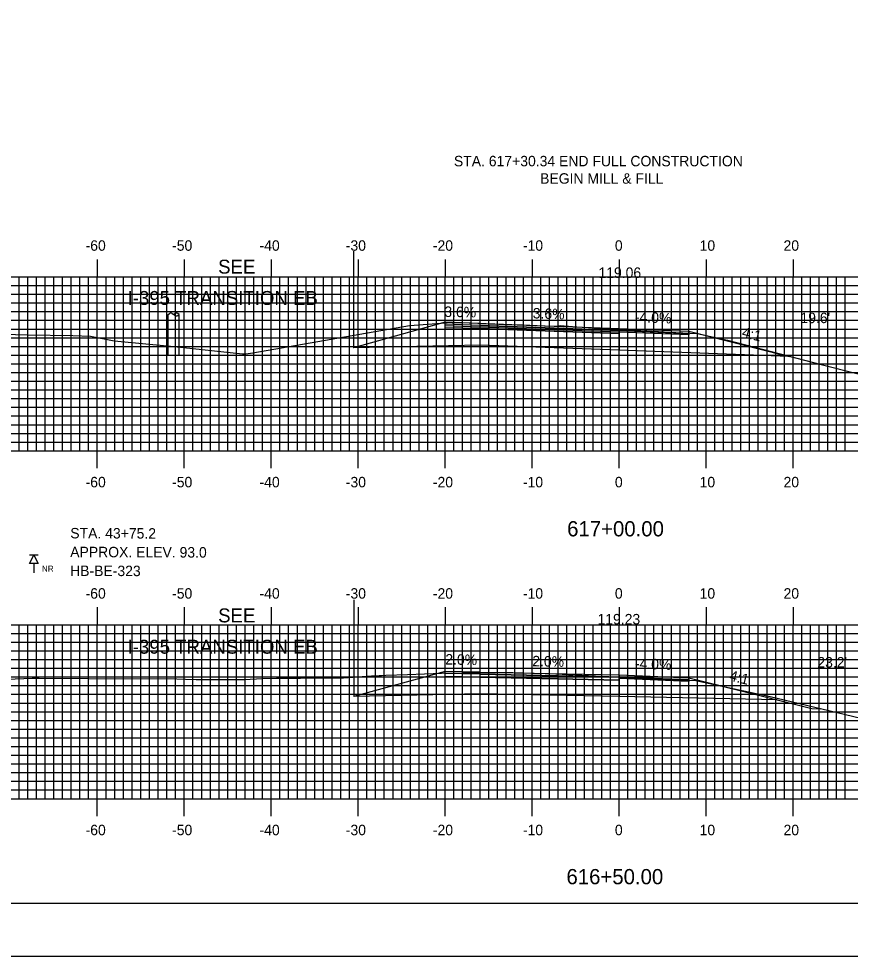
# Model space of a CAD drawing. Extents: x 844930 to 845273, y 363538 to 363758.
# Drawn here: x 845026.4 to 845122, y 363537.6 to 363645.4 of the extents above; entities that cross this region are included whole.
import ezdxf

# ---------------------------------------------------------------- set-up
doc = ezdxf.new("R2010")
doc.units = 0
for name, color, linetype in [('ANNOTATION', 7, 'Continuous'), ('BORDER', 7, 'Continuous'), ('BORING - NO REFUSAL', 7, 'Continuous'), ('D_Drainage_Text', 7, 'Continuous'), ('D_Roadway_Centerline_Text', 7, 'Continuous'), ('D_Roadway_Edge_Shoulder', 7, 'Continuous'), ('D_Roadway_Edge_TW', 7, 'Continuous'), ('D_Roadway_FinishedGrade', 7, 'Continuous'), ('D_Roadway_Pavement', 7, 'Continuous'), ('D_Roadway_SlopeLines', 7, 'Continuous'), ('D_Roadway_SubGrade', 7, 'Continuous'), ('D_Text_Standard', 7, 'Continuous'), ('H_V ANNOTATION', 7, 'Continuous'), ('M_Roadway_Centerline', 7, 'Continuous'), ('MAJOR', 7, 'Continuous'), ('MINOR', 7, 'Continuous'), ('PLOT BOUNDARY', 7, 'Continuous'), ('S_Roadway_Centerline', 7, 'Continuous'), ('S_Utilities_Pole_StreetLight', 7, 'Continuous')]:
    doc.layers.add(name, color=color, linetype=linetype)

msp = doc.modelspace()

# ---------------------------------------------------------------- linework, layer by layer
at = {"layer": 'BORDER'}
msp.add_lwpolyline([(844945.88, 363543.72), (845265.88, 363543.72), (845265.88, 363753.72), (844945.88, 363753.72)], close=True, dxfattribs=at)
at = {"layer": 'BORING - NO REFUSAL'}
for p, q in [((845028.66, 363583.72), (845027.7, 363583.72)), ((845028.18, 363582.76), (845028.18, 363581.7))]:
    msp.add_line(p, q, dxfattribs=at)
msp.add_lwpolyline([(845028.18, 363583.72), (845028.66, 363582.76), (845027.7, 363582.76)], close=True, dxfattribs=at)
at = {"layer": 'D_Roadway_Edge_Shoulder'}
for points in [[(845095.48, 363609.79), (845103.48, 363609.47), (845103.48, 363609.22), (845095.48, 363609.54)], [(845095.48, 363569.95), (845103.48, 363569.63), (845103.48, 363569.38), (845095.48, 363569.7)]]:
    msp.add_lwpolyline(points, close=True, dxfattribs=at)
at = {"layer": 'D_Roadway_Edge_TW'}
for points in [[(845079.48, 363610.36), (845095.48, 363609.79), (845095.48, 363609.54), (845079.48, 363610.11)], [(845079.48, 363570.27), (845095.48, 363569.95), (845095.48, 363569.7), (845079.48, 363570.02)]]:
    msp.add_lwpolyline(points, close=True, dxfattribs=at)
at = {"layer": 'D_Roadway_FinishedGrade'}
for p, q in [((845079.48, 363610.11), (845075.48, 363610.26)), ((845095.48, 363609.37), (845079.48, 363609.95)), ((845079.48, 363607.86), (845064.95, 363607.57)), ((845079.48, 363570.27), (845075.48, 363570.35)), ((845079.48, 363570.02), (845075.48, 363570.1)), ((845079.48, 363567.77), (845064.96, 363567.48))]:
    msp.add_line(p, q, dxfattribs=at)
for points in [[(845079.48, 363610.36), (845075.48, 363610.51), (845064.95, 363607.57)], [(845079.48, 363609.95), (845079.48, 363609.95), (845075.48, 363610.09), (845075.48, 363610.51)], [(845079.48, 363609.78), (845075.48, 363609.86), (845075.48, 363610.09)], [(845079.48, 363569.68), (845075.48, 363569.76), (845075.48, 363570.35), (845064.96, 363567.48)], [(845113.65, 363567.08), (845117.65, 363566.08), (845118.68, 363566.06)]]:
    msp.add_lwpolyline(points, dxfattribs=at)
at = {"layer": 'D_Roadway_Pavement'}
for points in [[(845079.48, 363610.11), (845095.48, 363609.54), (845095.48, 363609.2), (845079.48, 363609.78)], [(845095.48, 363609.54), (845103.48, 363609.22), (845103.48, 363609.05), (845095.48, 363609.37)], [(845079.48, 363570.02), (845095.48, 363569.7), (845095.48, 363569.36), (845079.48, 363569.68)], [(845095.48, 363569.7), (845103.48, 363569.38), (845103.48, 363569.21), (845095.48, 363569.53)]]:
    msp.add_lwpolyline(points, close=True, dxfattribs=at)
for points in [[(845095.48, 363609.54), (845095.48, 363609.2)], [(845095.48, 363609.54), (845095.48, 363609.2)], [(845095.48, 363569.7), (845095.48, 363569.36)], [(845095.48, 363569.7), (845095.48, 363569.36)]]:
    msp.add_lwpolyline(points, dxfattribs=at)
at = {"layer": 'D_Roadway_SlopeLines'}
for points in [[(845103.48, 363609.47), (845104.98, 363609.09)], [(845103.48, 363569.63), (845107.57, 363568.6)]]:
    msp.add_lwpolyline(points, dxfattribs=at)
at = {"layer": 'D_Roadway_SubGrade'}
for p, q in [((845064.95, 363618.67), (845064.95, 363607.57)), ((845064.96, 363578.57), (845064.96, 363567.48))]:
    msp.add_line(p, q, dxfattribs=at)
for points in [[(845079.48, 363609.78), (845095.48, 363609.2), (845095.48, 363607.29), (845079.48, 363607.86)], [(845095.48, 363609.2), (845095.48, 363609.54), (845103.48, 363609.22), (845103.48, 363609.47), (845115.03, 363606.58), (845095.48, 363607.29)], [(845079.48, 363569.68), (845095.48, 363569.36), (845095.48, 363567.45), (845079.48, 363567.77)], [(845095.48, 363569.36), (845095.48, 363569.7), (845103.48, 363569.38), (845103.48, 363569.63), (845113.65, 363567.08), (845095.48, 363567.45)]]:
    msp.add_lwpolyline(points, close=True, dxfattribs=at)
at = {"layer": 'MAJOR'}
for p, q in [((845035.48, 363617.73), (845035.48, 363615.72)), ((845045.48, 363617.73), (845045.48, 363615.72)), ((845055.48, 363617.73), (845055.48, 363615.72)), ((845065.48, 363617.73), (845065.48, 363615.72)), ((845075.48, 363617.73), (845075.48, 363615.72)), ((845085.48, 363617.73), (845085.48, 363615.72)), ((845095.48, 363617.73), (845095.48, 363615.72)), ((845105.48, 363617.73), (845105.48, 363615.72)), ((845115.48, 363617.73), (845115.48, 363615.72)), ((844955.48, 363615.72), (845235.48, 363615.72)), ((844955.48, 363615.72), (845235.48, 363615.72)), ((845035.48, 363595.72), (845035.48, 363615.72)), ((845045.48, 363595.72), (845045.48, 363615.72)), ((845055.48, 363595.72), (845055.48, 363615.72)), ((845065.48, 363595.72), (845065.48, 363615.72)), ((845075.48, 363595.72), (845075.48, 363615.72)), ((845085.48, 363595.72), (845085.48, 363615.72)), ((845095.48, 363595.72), (845095.48, 363615.72)), ((845105.48, 363595.72), (845105.48, 363615.72)), ((845115.48, 363595.72), (845115.48, 363615.72)), ((844955.48, 363610.72), (845235.48, 363610.72)), ((844955.48, 363605.72), (845235.48, 363605.72)), ((844955.48, 363600.72), (845235.48, 363600.72)), ((844955.48, 363595.72), (845235.48, 363595.72)), ((844955.48, 363595.72), (845235.48, 363595.72)), ((845035.48, 363593.72), (845035.48, 363595.72)), ((845045.48, 363593.72), (845045.48, 363595.72)), ((845055.48, 363593.72), (845055.48, 363595.72)), ((845065.48, 363593.72), (845065.48, 363595.72)), ((845075.48, 363593.72), (845075.48, 363595.72)), ((845085.48, 363593.72), (845085.48, 363595.72)), ((845095.48, 363593.72), (845095.48, 363595.72)), ((845105.48, 363593.72), (845105.48, 363595.72)), ((845115.48, 363593.72), (845115.48, 363595.72)), ((845035.48, 363577.73), (845035.48, 363575.72)), ((845045.48, 363577.73), (845045.48, 363575.72)), ((845055.48, 363577.73), (845055.48, 363575.72)), ((845065.48, 363577.73), (845065.48, 363575.72)), ((845075.48, 363577.73), (845075.48, 363575.72)), ((845085.48, 363577.73), (845085.48, 363575.72)), ((845095.48, 363577.73), (845095.48, 363575.72)), ((845105.48, 363577.73), (845105.48, 363575.72)), ((845115.48, 363577.73), (845115.48, 363575.72)), ((844955.48, 363575.72), (845235.48, 363575.72)), ((844955.48, 363575.72), (845235.48, 363575.72)), ((845035.48, 363555.72), (845035.48, 363575.72)), ((845045.48, 363555.72), (845045.48, 363575.72)), ((845055.48, 363555.72), (845055.48, 363575.72)), ((845065.48, 363555.72), (845065.48, 363575.72)), ((845075.48, 363555.72), (845075.48, 363575.72)), ((845085.48, 363555.72), (845085.48, 363575.72)), ((845095.48, 363555.72), (845095.48, 363575.72)), ((845105.48, 363555.72), (845105.48, 363575.72)), ((845115.48, 363555.72), (845115.48, 363575.72)), ((844955.48, 363570.72), (845235.48, 363570.72)), ((844955.48, 363565.72), (845235.48, 363565.72)), ((844955.48, 363560.72), (845235.48, 363560.72)), ((844955.48, 363555.72), (845235.48, 363555.72)), ((844955.48, 363555.72), (845235.48, 363555.72)), ((845035.48, 363553.72), (845035.48, 363555.72)), ((845045.48, 363553.72), (845045.48, 363555.72)), ((845055.48, 363553.72), (845055.48, 363555.72)), ((845065.48, 363553.72), (845065.48, 363555.72)), ((845075.48, 363553.72), (845075.48, 363555.72)), ((845085.48, 363553.72), (845085.48, 363555.72)), ((845095.48, 363553.72), (845095.48, 363555.72)), ((845105.48, 363553.72), (845105.48, 363555.72)), ((845115.48, 363553.72), (845115.48, 363555.72))]:
    msp.add_line(p, q, dxfattribs=at)
at = {"layer": 'MINOR'}
for p, q in [((845026.48, 363595.72), (845026.48, 363615.72)), ((845027.48, 363595.72), (845027.48, 363615.72)), ((845028.48, 363595.72), (845028.48, 363615.72)), ((845029.48, 363595.72), (845029.48, 363615.72)), ((845030.48, 363595.72), (845030.48, 363615.72)), ((845031.48, 363595.72), (845031.48, 363615.72)), ((845032.48, 363595.72), (845032.48, 363615.72)), ((845033.48, 363595.72), (845033.48, 363615.72)), ((845034.48, 363595.72), (845034.48, 363615.72)), ((845036.48, 363595.72), (845036.48, 363615.72)), ((845037.48, 363595.72), (845037.48, 363615.72)), ((845038.48, 363595.72), (845038.48, 363615.72)), ((845039.48, 363595.72), (845039.48, 363615.72)), ((845040.48, 363595.72), (845040.48, 363615.72)), ((845041.48, 363595.72), (845041.48, 363615.72)), ((845042.48, 363595.72), (845042.48, 363615.72)), ((845043.48, 363595.72), (845043.48, 363615.72)), ((845044.48, 363595.72), (845044.48, 363615.72)), ((845046.48, 363595.72), (845046.48, 363615.72)), ((845047.48, 363595.72), (845047.48, 363615.72)), ((845048.48, 363595.72), (845048.48, 363615.72)), ((845049.48, 363595.72), (845049.48, 363615.72)), ((845050.48, 363595.72), (845050.48, 363615.72)), ((845051.48, 363595.72), (845051.48, 363615.72)), ((845052.48, 363595.72), (845052.48, 363615.72)), ((845053.48, 363595.72), (845053.48, 363615.72)), ((845054.48, 363595.72), (845054.48, 363615.72)), ((845056.48, 363595.72), (845056.48, 363615.72)), ((845057.48, 363595.72), (845057.48, 363615.72)), ((845058.48, 363595.72), (845058.48, 363615.72)), ((845059.48, 363595.72), (845059.48, 363615.72)), ((845060.48, 363595.72), (845060.48, 363615.72)), ((845061.48, 363595.72), (845061.48, 363615.72)), ((845062.48, 363595.72), (845062.48, 363615.72)), ((845063.48, 363595.72), (845063.48, 363615.72)), ((845064.48, 363595.72), (845064.48, 363615.72)), ((845066.48, 363595.72), (845066.48, 363615.72)), ((845067.48, 363595.72), (845067.48, 363615.72)), ((845068.48, 363595.72), (845068.48, 363615.72)), ((845069.48, 363595.72), (845069.48, 363615.72)), ((845070.48, 363595.72), (845070.48, 363615.72)), ((845071.48, 363595.72), (845071.48, 363615.72)), ((845072.48, 363595.72), (845072.48, 363615.72)), ((845073.48, 363595.72), (845073.48, 363615.72)), ((845074.48, 363595.72), (845074.48, 363615.72)), ((845076.48, 363595.72), (845076.48, 363615.72)), ((845077.48, 363595.72), (845077.48, 363615.72)), ((845078.48, 363595.72), (845078.48, 363615.72)), ((845079.48, 363595.72), (845079.48, 363615.72)), ((845080.48, 363595.72), (845080.48, 363615.72)), ((845081.48, 363595.72), (845081.48, 363615.72)), ((845082.48, 363595.72), (845082.48, 363615.72)), ((845083.48, 363595.72), (845083.48, 363615.72)), ((845084.48, 363595.72), (845084.48, 363615.72)), ((845086.48, 363595.72), (845086.48, 363615.72)), ((845087.48, 363595.72), (845087.48, 363615.72)), ((845088.48, 363595.72), (845088.48, 363615.72)), ((845089.48, 363595.72), (845089.48, 363615.72)), ((845090.48, 363595.72), (845090.48, 363615.72)), ((845091.48, 363595.72), (845091.48, 363615.72)), ((845092.48, 363595.72), (845092.48, 363615.72)), ((845093.48, 363595.72), (845093.48, 363615.72)), ((845094.48, 363595.72), (845094.48, 363615.72)), ((845096.48, 363595.72), (845096.48, 363615.72)), ((845097.48, 363595.72), (845097.48, 363615.72)), ((845098.48, 363595.72), (845098.48, 363615.72)), ((845099.48, 363595.72), (845099.48, 363615.72)), ((845100.48, 363595.72), (845100.48, 363615.72)), ((845101.48, 363595.72), (845101.48, 363615.72)), ((845102.48, 363595.72), (845102.48, 363615.72)), ((845103.48, 363595.72), (845103.48, 363615.72)), ((845104.48, 363595.72), (845104.48, 363615.72)), ((845106.48, 363595.72), (845106.48, 363615.72)), ((845107.48, 363595.72), (845107.48, 363615.72)), ((845108.48, 363595.72), (845108.48, 363615.72)), ((845109.48, 363595.72), (845109.48, 363615.72)), ((845110.48, 363595.72), (845110.48, 363615.72)), ((845111.48, 363595.72), (845111.48, 363615.72)), ((845112.48, 363595.72), (845112.48, 363615.72)), ((845113.48, 363595.72), (845113.48, 363615.72)), ((845114.48, 363595.72), (845114.48, 363615.72)), ((845116.48, 363595.72), (845116.48, 363615.72)), ((845117.48, 363595.72), (845117.48, 363615.72)), ((845118.48, 363595.72), (845118.48, 363615.72)), ((845119.48, 363595.72), (845119.48, 363615.72)), ((845120.48, 363595.72), (845120.48, 363615.72)), ((845121.48, 363595.72), (845121.48, 363615.72)), ((844955.48, 363614.72), (845235.48, 363614.72)), ((844955.48, 363613.72), (845235.48, 363613.72)), ((844955.48, 363612.72), (845235.48, 363612.72)), ((844955.48, 363611.72), (845235.48, 363611.72)), ((844955.48, 363609.72), (845235.48, 363609.72)), ((844955.48, 363608.72), (845235.48, 363608.72)), ((844955.48, 363607.72), (845235.48, 363607.72)), ((844955.48, 363606.72), (845235.48, 363606.72)), ((844955.48, 363604.72), (845235.48, 363604.72)), ((844955.48, 363603.72), (845235.48, 363603.72)), ((844955.48, 363602.72), (845235.48, 363602.72)), ((844955.48, 363601.72), (845235.48, 363601.72)), ((844955.48, 363599.72), (845235.48, 363599.72)), ((844955.48, 363598.72), (845235.48, 363598.72)), ((844955.48, 363597.72), (845235.48, 363597.72)), ((844955.48, 363596.72), (845235.48, 363596.72)), ((845026.48, 363555.72), (845026.48, 363575.72)), ((845027.48, 363555.72), (845027.48, 363575.72)), ((845028.48, 363555.72), (845028.48, 363575.72)), ((845029.48, 363555.72), (845029.48, 363575.72)), ((845030.48, 363555.72), (845030.48, 363575.72)), ((845031.48, 363555.72), (845031.48, 363575.72)), ((845032.48, 363555.72), (845032.48, 363575.72)), ((845033.48, 363555.72), (845033.48, 363575.72)), ((845034.48, 363555.72), (845034.48, 363575.72)), ((845036.48, 363555.72), (845036.48, 363575.72)), ((845037.48, 363555.72), (845037.48, 363575.72)), ((845038.48, 363555.72), (845038.48, 363575.72)), ((845039.48, 363555.72), (845039.48, 363575.72)), ((845040.48, 363555.72), (845040.48, 363575.72)), ((845041.48, 363555.72), (845041.48, 363575.72)), ((845042.48, 363555.72), (845042.48, 363575.72)), ((845043.48, 363555.72), (845043.48, 363575.72)), ((845044.48, 363555.72), (845044.48, 363575.72)), ((845046.48, 363555.72), (845046.48, 363575.72)), ((845047.48, 363555.72), (845047.48, 363575.72)), ((845048.48, 363555.72), (845048.48, 363575.72)), ((845049.48, 363555.72), (845049.48, 363575.72)), ((845050.48, 363555.72), (845050.48, 363575.72)), ((845051.48, 363555.72), (845051.48, 363575.72)), ((845052.48, 363555.72), (845052.48, 363575.72)), ((845053.48, 363555.72), (845053.48, 363575.72)), ((845054.48, 363555.72), (845054.48, 363575.72)), ((845056.48, 363555.72), (845056.48, 363575.72)), ((845057.48, 363555.72), (845057.48, 363575.72)), ((845058.48, 363555.72), (845058.48, 363575.72)), ((845059.48, 363555.72), (845059.48, 363575.72)), ((845060.48, 363555.72), (845060.48, 363575.72)), ((845061.48, 363555.72), (845061.48, 363575.72)), ((845062.48, 363555.72), (845062.48, 363575.72)), ((845063.48, 363555.72), (845063.48, 363575.72)), ((845064.48, 363555.72), (845064.48, 363575.72)), ((845066.48, 363555.72), (845066.48, 363575.72)), ((845067.48, 363555.72), (845067.48, 363575.72)), ((845068.48, 363555.72), (845068.48, 363575.72)), ((845069.48, 363555.72), (845069.48, 363575.72)), ((845070.48, 363555.72), (845070.48, 363575.72)), ((845071.48, 363555.72), (845071.48, 363575.72)), ((845072.48, 363555.72), (845072.48, 363575.72)), ((845073.48, 363555.72), (845073.48, 363575.72)), ((845074.48, 363555.72), (845074.48, 363575.72)), ((845076.48, 363555.72), (845076.48, 363575.72)), ((845077.48, 363555.72), (845077.48, 363575.72)), ((845078.48, 363555.72), (845078.48, 363575.72)), ((845079.48, 363555.72), (845079.48, 363575.72)), ((845080.48, 363555.72), (845080.48, 363575.72)), ((845081.48, 363555.72), (845081.48, 363575.72)), ((845082.48, 363555.72), (845082.48, 363575.72)), ((845083.48, 363555.72), (845083.48, 363575.72)), ((845084.48, 363555.72), (845084.48, 363575.72)), ((845086.48, 363555.72), (845086.48, 363575.72)), ((845087.48, 363555.72), (845087.48, 363575.72)), ((845088.48, 363555.72), (845088.48, 363575.72)), ((845089.48, 363555.72), (845089.48, 363575.72)), ((845090.48, 363555.72), (845090.48, 363575.72)), ((845091.48, 363555.72), (845091.48, 363575.72)), ((845092.48, 363555.72), (845092.48, 363575.72)), ((845093.48, 363555.72), (845093.48, 363575.72)), ((845094.48, 363555.72), (845094.48, 363575.72)), ((845096.48, 363555.72), (845096.48, 363575.72)), ((845097.48, 363555.72), (845097.48, 363575.72)), ((845098.48, 363555.72), (845098.48, 363575.72)), ((845099.48, 363555.72), (845099.48, 363575.72)), ((845100.48, 363555.72), (845100.48, 363575.72)), ((845101.48, 363555.72), (845101.48, 363575.72)), ((845102.48, 363555.72), (845102.48, 363575.72)), ((845103.48, 363555.72), (845103.48, 363575.72)), ((845104.48, 363555.72), (845104.48, 363575.72)), ((845106.48, 363555.72), (845106.48, 363575.72)), ((845107.48, 363555.72), (845107.48, 363575.72)), ((845108.48, 363555.72), (845108.48, 363575.72)), ((845109.48, 363555.72), (845109.48, 363575.72)), ((845110.48, 363555.72), (845110.48, 363575.72)), ((845111.48, 363555.72), (845111.48, 363575.72)), ((845112.48, 363555.72), (845112.48, 363575.72)), ((845113.48, 363555.72), (845113.48, 363575.72)), ((845114.48, 363555.72), (845114.48, 363575.72)), ((845116.48, 363555.72), (845116.48, 363575.72)), ((845117.48, 363555.72), (845117.48, 363575.72)), ((845118.48, 363555.72), (845118.48, 363575.72)), ((845119.48, 363555.72), (845119.48, 363575.72)), ((845120.48, 363555.72), (845120.48, 363575.72)), ((845121.48, 363555.72), (845121.48, 363575.72)), ((844955.48, 363574.72), (845235.48, 363574.72)), ((844955.48, 363573.72), (845235.48, 363573.72)), ((844955.48, 363572.72), (845235.48, 363572.72)), ((844955.48, 363571.72), (845235.48, 363571.72)), ((844955.48, 363569.72), (845235.48, 363569.72)), ((844955.48, 363568.72), (845235.48, 363568.72)), ((844955.48, 363567.72), (845235.48, 363567.72)), ((844955.48, 363566.72), (845235.48, 363566.72)), ((844955.48, 363564.72), (845235.48, 363564.72)), ((844955.48, 363563.72), (845235.48, 363563.72)), ((844955.48, 363562.72), (845235.48, 363562.72)), ((844955.48, 363561.72), (845235.48, 363561.72)), ((844955.48, 363559.72), (845235.48, 363559.72)), ((844955.48, 363558.72), (845235.48, 363558.72)), ((844955.48, 363557.72), (845235.48, 363557.72)), ((844955.48, 363556.72), (845235.48, 363556.72))]:
    msp.add_line(p, q, dxfattribs=at)
at = {"layer": 'PLOT BOUNDARY'}
msp.add_lwpolyline([(844929.69, 363537.6), (845269.69, 363537.6), (845269.69, 363757.6), (844929.69, 363757.6)], close=True, dxfattribs=at)
at = {"layer": 'S_Roadway_Centerline'}
for points in [[(845020.28, 363609.26), (845027.48, 363609.04), (845032.67, 363608.97), (845034.71, 363608.88), (845037.41, 363608.38), (845044.31, 363607.7), (845052.16, 363606.88), (845052.56, 363606.86), (845053.35, 363606.99), (845071.37, 363610.14), (845075.03, 363610.39), (845076.04, 363610.5), (845076.1, 363610.49), (845076.29, 363610.48), (845078.24, 363610.43), (845084.14, 363610.21), (845084.38, 363610.2), (845086.88, 363610.1), (845088.13, 363610.04), (845088.55, 363610.1), (845088.69, 363610.11), (845090.6, 363609.97), (845101.98, 363609.32), (845104.43, 363609.21), (845107.94, 363608.45), (845118.72, 363605.64), (845127.06, 363603.52)], [(845019.18, 363569.24), (845027.98, 363569.56), (845028.57, 363569.58), (845028.6, 363569.58), (845028.81, 363569.57), (845034.44, 363569.54), (845044.62, 363569.49), (845045.6, 363569.47), (845046.84, 363569.44), (845048.98, 363569.41), (845051.01, 363569.41), (845052.36, 363569.43), (845054.49, 363569.53), (845056.1, 363569.56), (845058.83, 363569.57), (845062.63, 363569.62), (845063.78, 363569.63), (845066.99, 363569.84), (845067.9, 363569.88), (845068.14, 363569.89), (845068.65, 363569.91), (845071.13, 363570.01), (845075.06, 363570.14), (845077.49, 363570.2), (845078.18, 363570.21), (845083.25, 363570.22), (845088.18, 363570.06), (845088.2, 363570.08), (845089.66, 363569.99), (845095.07, 363569.74), (845099.2, 363569.49), (845101.91, 363569.37), (845103.27, 363569.31), (845104.12, 363569.35), (845112.83, 363567.47), (845121.35, 363565.42), (845128.67, 363563.67)]]:
    msp.add_lwpolyline(points, dxfattribs=at)
at = {"layer": 'S_Utilities_Pole_StreetLight'}
for p, q in [((845043.63, 363611.4), (845043.79, 363611.51)), ((845043.63, 363606.78), (845043.63, 363611.4)), ((845044.1, 363611.51), (845044.26, 363611.4)), ((845044.41, 363611.51), (845044.26, 363611.4)), ((845044.26, 363611.4), (845044.41, 363611.29)), ((845044.88, 363611.4), (845044.73, 363611.51)), ((845044.73, 363611.29), (845044.88, 363611.4)), ((845044.88, 363606.78), (845044.88, 363611.4))]:
    msp.add_line(p, q, dxfattribs=at)
for centre, start, end in [((845043.94, 363611.29), 90, 125.2644), ((845043.94, 363611.29), 54.7356, 90), ((845044.57, 363611.29), 90, 125.2644), ((845044.57, 363611.51), 234.7356, 270), ((845044.57, 363611.29), 54.7356, 90), ((845044.57, 363611.51), 270, 305.2644)]:
    msp.add_arc(centre, 0.271, start, end, dxfattribs=at)

# ---------------------------------------------------------------- texts
at = {"layer": 'ANNOTATION'}
for s, p in [('SEE', (845049.37, 363616.09)), ('I-395 TRANSITION EB', (845038.96, 363612.49)), ('SEE', (845049.37, 363575.99)), ('I-395 TRANSITION EB', (845038.96, 363572.39))]:
    msp.add_text(s, height=1.6, dxfattribs=at).set_placement(p)
for s, rotation, p in [('3.6%', 359.0259, (845075.37, 363611.12)), ('3.6%', 357.9273, (845085.53, 363610.95)), ('-4.0%', 357.7094, (845097.27, 363610.52)), ('4:1', 345.9638, (845109.51, 363608.82)), ('2.0%', 358.8542, (845075.48, 363571.15)), ('2.0%', 358.8542, (845085.48, 363570.95)), ('-4.0%', 357.7094, (845097.27, 363570.68)), ('4:1', 345.9638, (845108.07, 363569.34))]:
    msp.add_text(s, height=1.2, rotation=rotation, dxfattribs=at).set_placement(p)
at = {"layer": 'BORING - NO REFUSAL'}
for s, p in [('STA. 43+75.2', (845032.37, 363585.65)), ('APPROX. ELEV. 93.0', (845032.36, 363583.49)), ('HB-BE-323', (845032.35, 363581.33))]:
    msp.add_text(s, height=1.2, rotation=359.8142, dxfattribs=at).set_placement(p)
msp.add_text('NR', height=0.7, dxfattribs=at).set_placement((845029.11, 363581.81))
at = {"layer": 'D_Drainage_Text'}
for s, p in [('STA. 617+30.34 END FULL CONSTRUCTION', (845076.48, 363628.43)), ('BEGIN MILL & FILL', (845086.39, 363626.43))]:
    msp.add_text(s, height=1.2, dxfattribs=at).set_placement(p)
at = {"layer": 'D_Roadway_Centerline_Text'}
for s, p in [('119.06', (845093.1, 363615.6)), ('119.23', (845092.99, 363575.76))]:
    msp.add_text(s, height=1.2, dxfattribs=at).set_placement(p)
at = {"layer": 'D_Text_Standard'}
for s, p in [("19.6'", (845116.32, 363610.4)), ("23.2'", (845118.27, 363570.8))]:
    msp.add_text(s, height=1.2, dxfattribs=at).set_placement(p)
at = {"layer": 'H_V ANNOTATION'}
for s, height, p in [('-60', 1.2, (845034.13, 363618.72)), ('-50', 1.2, (845044.08, 363618.72)), ('-40', 1.2, (845054.13, 363618.72)), ('-30', 1.2, (845064.05, 363618.72)), ('-20', 1.2, (845074.06, 363618.72)), ('-10', 1.2, (845084.41, 363618.72)), ('0', 1.2, (845094.99, 363618.72)), ('10', 1.2, (845104.73, 363618.72)), ('20', 1.2, (845114.38, 363618.72)), ('-60', 1.2, (845034.13, 363591.52)), ('-50', 1.2, (845044.08, 363591.52)), ('-40', 1.2, (845054.13, 363591.52)), ('-30', 1.2, (845064.05, 363591.52)), ('-20', 1.2, (845074.06, 363591.52)), ('-10', 1.2, (845084.41, 363591.52)), ('0', 1.2, (845094.99, 363591.52)), ('10', 1.2, (845104.73, 363591.52)), ('20', 1.2, (845114.38, 363591.52)), ('617+00.00', 1.75, (845089.5, 363585.88)), ('-60', 1.2, (845034.13, 363578.72)), ('-50', 1.2, (845044.08, 363578.72)), ('-40', 1.2, (845054.13, 363578.72)), ('-30', 1.2, (845064.05, 363578.72)), ('-20', 1.2, (845074.06, 363578.72)), ('-10', 1.2, (845084.41, 363578.72)), ('0', 1.2, (845094.99, 363578.72)), ('10', 1.2, (845104.73, 363578.72)), ('20', 1.2, (845114.38, 363578.72)), ('-60', 1.2, (845034.13, 363551.52)), ('-50', 1.2, (845044.08, 363551.52)), ('-40', 1.2, (845054.13, 363551.52)), ('-30', 1.2, (845064.05, 363551.52)), ('-20', 1.2, (845074.06, 363551.52)), ('-10', 1.2, (845084.41, 363551.52)), ('0', 1.2, (845094.99, 363551.52)), ('10', 1.2, (845104.73, 363551.52)), ('20', 1.2, (845114.38, 363551.52)), ('616+50.00', 1.75, (845089.42, 363545.88))]:
    msp.add_text(s, height=height, dxfattribs=at).set_placement(p)
at = {"layer": 'M_Roadway_Centerline'}
for s, p in [('C', (845088.68, 363610.11)), ('L', (845088.69, 363610.1)), ('C', (845028.6, 363569.58)), ('C', (845088.2, 363570.08)), ('L', (845088.2, 363570.08)), ('L', (845028.6, 363569.58))]:
    msp.add_text(s, height=0.0146, dxfattribs=at).set_placement(p)

doc.saveas('drawing.dxf')
